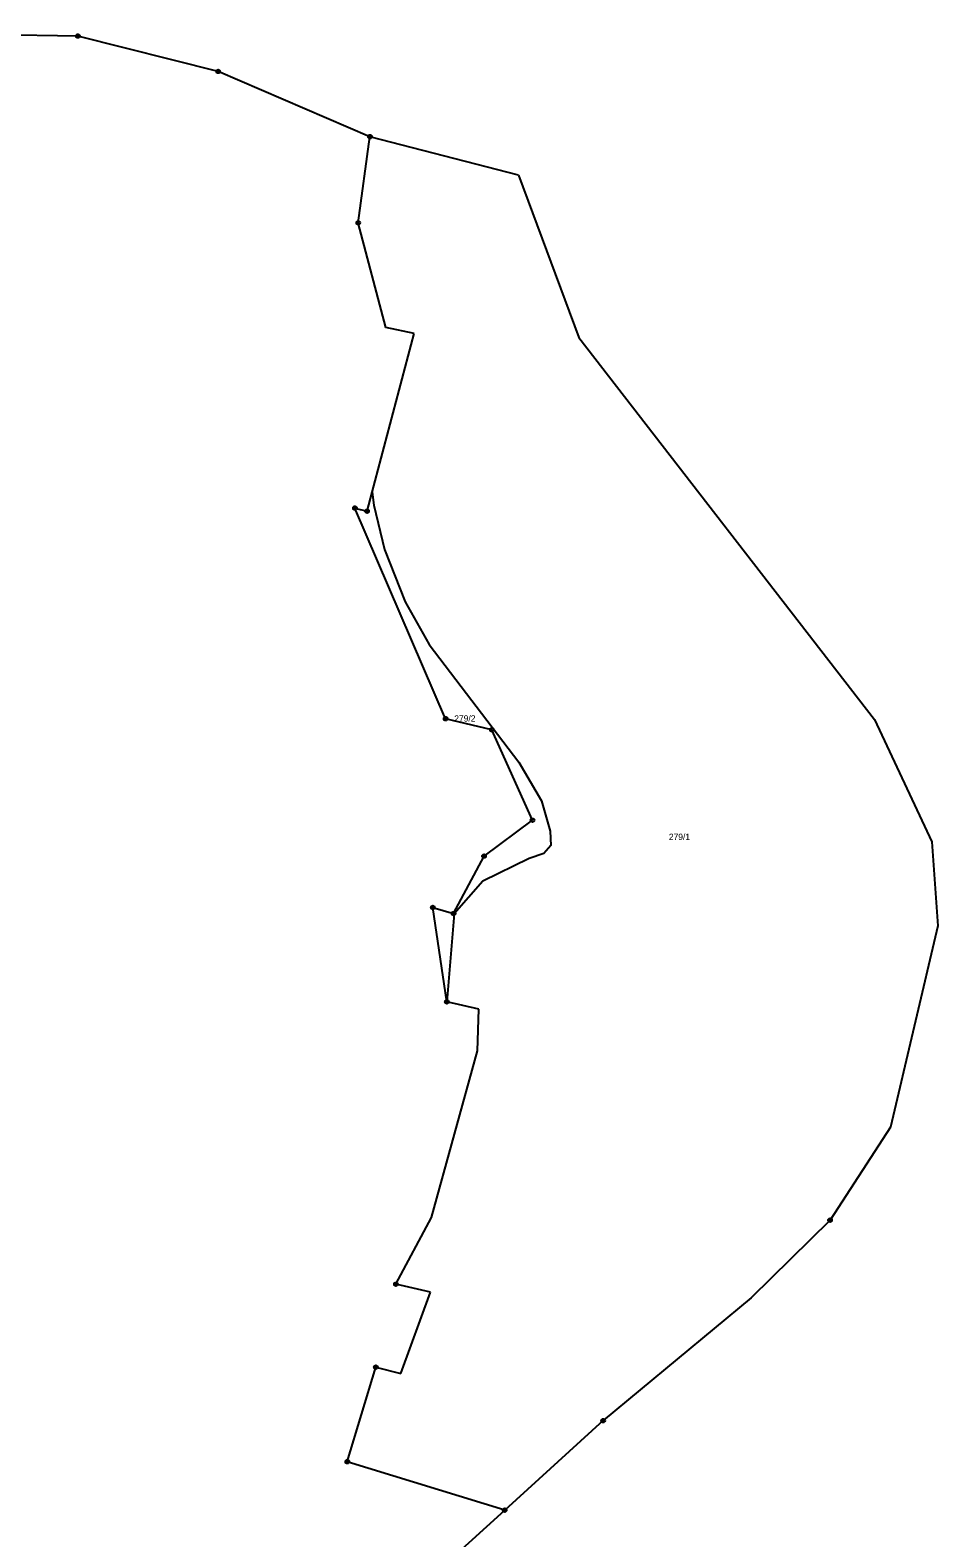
# Model space of a CAD drawing. Extents: x -885985 to -883535, y -1030025 to -1027941.
# Drawn here: x -883779 to -883535.4, y -1028348.3 to -1027943.7 of the extents above; entities that cross this region are included whole.
import ezdxf

# ---------------------------------------------------------------- set-up
doc = ezdxf.new("R2010")
doc.units = 0
doc.header["$LTSCALE"] = 0.68
doc.layers.add('1', color=7, linetype='Continuous', lineweight=25)
doc.layers.add('8', color=7, linetype='Continuous', lineweight=25)
doc.layers.add('2', color=7, linetype='Continuous')

msp = doc.modelspace()

# ---------------------------------------------------------------- linework, layer by layer
at = {"layer": '1'}
for p, q in [((-883766.18, -1027945.32), (-883886.44, -1027943.74)), ((-883728.51, -1027954.81), (-883766.18, -1027945.32)), ((-883687.79, -1027972.32), (-883728.51, -1027954.81)), ((-883690.94, -1027995.41), (-883687.79, -1027972.32)), ((-883647.91, -1027982.61), (-883687.79, -1027972.32)), ((-883647.91, -1027982.61), (-883631.69, -1028026.19)), ((-883683.57, -1028023.54), (-883690.94, -1027995.41)), ((-883675.95, -1028025.16), (-883683.57, -1028023.54)), ((-883687.22, -1028067.67), (-883675.95, -1028025.16)), ((-883688.58, -1028072.82), (-883687.22, -1028067.67)), ((-883687.22, -1028067.67), (-883686.77, -1028071.17)), ((-883691.84, -1028071.96), (-883688.58, -1028072.82)), ((-883667.48, -1028128.49), (-883691.84, -1028071.96)), ((-883686.77, -1028071.17), (-883683.93, -1028083.09)), ((-883683.93, -1028083.09), (-883678.3, -1028097.11)), ((-883678.3, -1028097.11), (-883671.94, -1028108.61)), ((-883671.94, -1028108.61), (-883647.82, -1028140.12)), ((-883655.05, -1028131.49), (-883667.48, -1028128.49)), ((-883644.17, -1028155.73), (-883655.05, -1028131.49)), ((-883647.82, -1028140.12), (-883641.78, -1028150.56)), ((-883641.78, -1028150.56), (-883639.45, -1028158.63)), ((-883657.17, -1028165.35), (-883644.17, -1028155.73)), ((-883639.45, -1028158.63), (-883639.28, -1028162.55)), ((-883641.1, -1028164.69), (-883645.09, -1028165.97)), ((-883639.28, -1028162.55), (-883641.1, -1028164.69)), ((-883537.02, -1028161.5), (-883535.36, -1028184.05)), ((-883665.33, -1028180.77), (-883657.17, -1028165.35)), ((-883645.09, -1028165.97), (-883657.48, -1028172.04)), ((-883657.48, -1028172.04), (-883665.23, -1028180.89)), ((-883667.17, -1028204.48), (-883670.92, -1028179.12)), ((-883670.92, -1028179.12), (-883665.33, -1028180.77)), ((-883665.23, -1028180.89), (-883667.17, -1028204.48)), ((-883535.36, -1028184.05), (-883548.05, -1028238.08)), ((-883658.59, -1028206.39), (-883667.17, -1028204.48)), ((-883658.91, -1028217.65), (-883658.59, -1028206.39)), ((-883671.23, -1028262.29), (-883658.91, -1028217.65)), ((-883548.05, -1028238.08), (-883564.3, -1028263.05)), ((-883680.82, -1028280.23), (-883671.23, -1028262.29)), ((-883564.3, -1028263.05), (-883585.44, -1028283.91)), ((-883671.52, -1028282.39), (-883680.82, -1028280.23)), ((-883679.48, -1028304.17), (-883671.52, -1028282.39)), ((-883585.44, -1028283.91), (-883625.19, -1028316.84)), ((-883693.87, -1028327.85), (-883686.21, -1028302.49)), ((-883686.21, -1028302.49), (-883679.48, -1028304.17)), ((-883625.19, -1028316.84), (-883651.63, -1028340.85)), ((-883651.63, -1028340.85), (-883693.87, -1028327.85)), ((-883673.58, -1028360.79), (-883651.63, -1028340.85))]:
    msp.add_line(p, q, dxfattribs=at)
msp.add_lwpolyline([(-883631.69, -1028026.19), (-883552.36, -1028128.71), (-883537.02, -1028161.5)], dxfattribs=at)
at = {"layer": '8'}
for centre, radius in [((-883766.18, -1027945.3199), 0.5), ((-883766.18, -1027945.3199), 0.0303), ((-883728.51, -1027954.8099), 0.5), ((-883728.51, -1027954.8099), 0.0303), ((-883687.79, -1027972.3199), 0.5), ((-883687.79, -1027972.3199), 0.0303), ((-883690.94, -1027995.4099), 0.5), ((-883690.94, -1027995.4099), 0.0303), ((-883691.84, -1028071.9599), 0.5), ((-883691.84, -1028071.9599), 0.0303), ((-883688.58, -1028072.8199), 0.5), ((-883688.58, -1028072.8199), 0.0303), ((-883667.48, -1028128.4899), 0.5), ((-883667.48, -1028128.4899), 0.0303), ((-883655.05, -1028131.4899), 0.5), ((-883655.05, -1028131.4899), 0.0303), ((-883644.17, -1028155.7299), 0.5), ((-883644.17, -1028155.7299), 0.0303), ((-883657.17, -1028165.3499), 0.5), ((-883657.17, -1028165.3499), 0.0303), ((-883670.92, -1028179.1199), 0.5), ((-883670.92, -1028179.1199), 0.0303), ((-883665.33, -1028180.7699), 0.5), ((-883665.33, -1028180.7699), 0.0303), ((-883667.17, -1028204.4799), 0.5), ((-883667.17, -1028204.4799), 0.0303), ((-883564.3, -1028263.0499), 0.5), ((-883564.3, -1028263.0499), 0.0303), ((-883680.82, -1028280.2299), 0.5), ((-883680.82, -1028280.2299), 0.0303), ((-883686.21, -1028302.4899), 0.5), ((-883686.21, -1028302.4899), 0.0303), ((-883625.19, -1028316.8399), 0.5), ((-883625.19, -1028316.8399), 0.0303), ((-883693.87, -1028327.8499), 0.5), ((-883693.87, -1028327.8499), 0.0303), ((-883651.63, -1028340.8499), 0.5), ((-883651.63, -1028340.8499), 0.0303)]:
    msp.add_circle(centre, radius, dxfattribs=at)

# ---------------------------------------------------------------- texts
at = {"layer": '2'}
for s, p in [('279/2', (-883665.16, -1028129.275)), ('279/1', (-883607.56, -1028161.045))]:
    msp.add_text(s, height=1.7, dxfattribs=at).set_placement(p)

doc.saveas('drawing.dxf')
